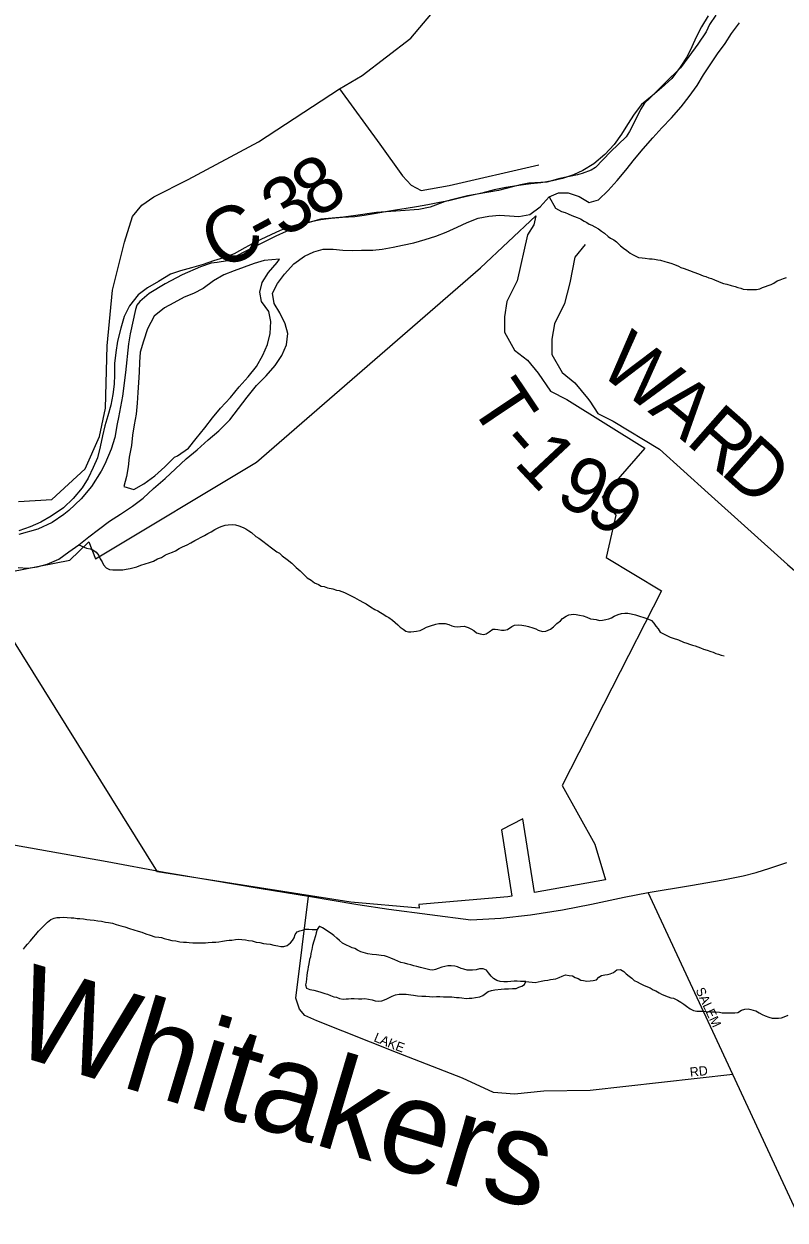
# Model space of a CAD drawing. Extents: x 0 to 1064, y 0 to 440.
# Drawn here: x 322.39 to 334.77, y 145.11 to 164.57 of the extents above; entities that cross this region are included whole.
import ezdxf

# ---------------------------------------------------------------- set-up
doc = ezdxf.new("R2010")
doc.units = 0
for name, color, linetype in [('GM_X_Corporation', 7, 'Continuous'), ('GM_X_County_Road', 7, 'Continuous'), ('GM_X_County_Road_Text', 7, 'Continuous'), ('GM_X_Major_River', 7, 'Continuous'), ('GM_X_Minor_Lake', 7, 'Continuous'), ('GM_X_Minor_River', 7, 'Continuous'), ('GM_X_Minor_River_Text', 7, 'Continuous'), ('GM_X_Section', 7, 'Continuous'), ('GM_X_Township_Road', 7, 'Continuous'), ('GM_X_Township_Road_Text', 7, 'Continuous'), ('GM_X_Township_Subdivision', 7, 'Continuous'), ('GM_X_Township_Subdivision_Text', 7, 'Continuous'), ('GM_X_US_Route', 7, 'Continuous')]:
    doc.layers.add(name, color=color, linetype=linetype)

msp = doc.modelspace()

# ---------------------------------------------------------------- linework, layer by layer
at = {"layer": 'GM_X_Corporation'}
msp.add_lwpolyline([(321.667, 155.562), (323.139, 155.848), (323.451, 156.149), (323.559, 155.869), (326.179, 157.444), (329.818, 160.607), (330.722, 161.45), (330.686, 161.304), (330.583, 161.143), (330.416, 160.393), (330.249, 160.06), (330.208, 159.809), (330.208, 159.559), (330.374, 159.268), (330.583, 159.101), (330.76, 158.891), (330.958, 158.601), (331.227, 158.466), (332.492, 157.672), (331.8, 156.876), (332.022, 156.581), (331.864, 155.893), (332.762, 155.353), (331.147, 152.183), (331.678, 151.227), (331.855, 150.647), (330.7, 150.443), (330.51, 151.641), (330.159, 151.462), (330.33, 150.384), (330.267, 150.373), (328.815, 150.246), (328.825, 150.186), (327.711, 150.284), (324.568, 150.782), (321.795, 155.22)], dxfattribs=at)
at = {"layer": 'GM_X_County_Road'}
msp.add_lwpolyline([(322.303, 156.803), (322.846, 156.838), (323.389, 157.338), (323.622, 157.859), (323.719, 158.325), (323.747, 159.339), (323.835, 160.244), (324.03, 161.024), (324.16, 161.44), (324.311, 161.625), (324.509, 161.763), (325.065, 162.043), (326.207, 162.655), (327.526, 163.517), (327.896, 163.733), (328.689, 164.344), (329.099, 164.829)], dxfattribs=at)
at = {"layer": 'GM_X_Major_River'}
for points in [[(333.522, 164.706), (333.415, 164.526), (333.326, 164.357), (333.256, 164.2), (333.179, 164.044), (333.066, 163.87), (332.934, 163.684), (332.766, 163.535), (332.611, 163.405), (332.437, 163.262), (332.318, 163.106), (332.21, 162.938), (332.116, 162.782), (331.996, 162.614), (331.84, 162.447), (331.666, 162.299), (331.487, 162.187), (331.333, 162.117), (331.155, 162.06), (330.989, 162.021), (330.799, 161.988), (330.64, 161.973), (330.481, 161.952), (330.23, 161.915), (330.04, 161.876), (329.844, 161.82), (329.691, 161.786), (329.501, 161.742), (329.304, 161.697), (329.151, 161.67), (328.961, 161.631), (328.778, 161.598), (328.612, 161.571), (328.435, 161.545), (328.276, 161.518), (328.092, 161.485), (327.927, 161.458), (327.774, 161.437), (327.578, 161.423), (327.389, 161.408), (327.223, 161.388), (327.064, 161.354), (326.911, 161.327), (326.739, 161.276), (326.561, 161.213), (326.407, 161.143), (326.166, 161.026), (325.988, 160.933), (325.815, 160.833), (325.642, 160.77), (325.477, 160.718), (325.311, 160.661), (325.12, 160.604), (324.942, 160.559), (324.777, 160.502)], [(326.645, 159.696), (326.557, 159.874), (326.463, 160.028), (326.436, 160.193), (326.518, 160.35), (326.632, 160.505), (326.781, 160.673), (326.955, 160.797), (327.109, 160.867), (327.262, 160.912), (327.421, 160.909), (327.579, 160.893), (327.732, 160.89), (327.884, 160.893), (328.067, 160.895), (328.22, 160.91), (328.398, 160.943), (328.551, 160.976), (328.735, 161.015), (328.919, 161.066), (329.091, 161.123), (329.263, 161.187), (329.442, 161.268), (329.602, 161.344), (329.781, 161.413), (329.958, 161.446), (330.129, 161.461), (330.294, 161.451), (330.446, 161.442), (330.624, 161.475), (330.791, 161.599), (330.935, 161.76), (331.089, 161.824), (331.247, 161.827), (331.423, 161.768), (331.586, 161.668), (331.739, 161.713), (331.895, 161.862), (332.045, 162.029), (332.183, 162.197), (332.327, 162.376), (332.464, 162.544), (332.621, 162.723), (332.771, 162.884), (332.926, 163.045), (333.083, 163.224), (333.214, 163.392), (333.346, 163.572), (333.448, 163.746), (333.567, 163.926), (333.674, 164.088), (333.8, 164.256), (333.901, 164.418), (334.033, 164.592)], [(326.551, 160.744), (326.301, 160.725), (326.141, 160.674), (325.975, 160.617), (325.815, 160.559), (325.643, 160.49), (325.476, 160.396), (325.309, 160.272), (325.154, 160.19), (325.001, 160.126), (324.834, 160.038), (324.68, 159.956), (324.512, 159.82), (324.404, 159.615), (324.339, 159.41), (324.286, 159.234), (324.271, 159.07), (324.267, 158.906), (324.258, 158.742), (324.248, 158.578), (324.238, 158.402), (324.217, 158.226), (324.188, 158.05), (324.161, 157.886), (324.145, 157.716), (324.104, 157.528), (324.089, 157.37), (324.061, 157.213), (324.021, 157.049), (324.179, 156.997), (324.345, 157.091), (324.525, 157.221), (324.687, 157.37), (324.843, 157.525), (324.892, 157.548)], [(324.892, 157.548), (325.071, 157.672), (325.197, 157.828), (325.335, 158.001), (325.46, 158.163), (325.591, 158.325), (325.754, 158.498), (325.892, 158.671), (326.041, 158.832), (326.179, 159), (326.281, 159.186), (326.357, 159.361), (326.398, 159.537), (326.408, 159.731), (326.375, 159.896), (326.256, 160.057), (326.229, 160.21), (326.269, 160.367), (326.37, 160.529), (326.513, 160.691), (326.551, 160.744)], [(324.777, 160.502), (324.585, 160.384), (324.406, 160.278), (324.251, 160.166), (324.113, 159.986), (324.024, 159.812), (323.971, 159.624), (323.918, 159.412), (323.89, 159.23), (323.868, 159.048), (323.864, 158.866), (323.861, 158.714), (323.839, 158.544), (323.805, 158.374), (323.758, 158.199), (323.712, 158.035), (323.672, 157.872), (323.632, 157.696), (323.592, 157.515), (323.521, 157.358), (323.438, 157.183), (323.343, 157.027), (323.193, 156.854), (323.038, 156.699), (322.839, 156.563), (322.667, 156.469), (322.494, 156.394), (322.31, 156.325)], [(322.297, 155.728), (322.456, 155.719), (322.609, 155.74), (322.774, 155.785), (322.959, 155.867), (323.126, 155.985), (323.287, 156.097), (323.449, 156.228), (323.604, 156.346), (323.784, 156.482), (323.963, 156.6), (324.161, 156.73), (324.334, 156.86), (324.502, 157.015), (324.689, 157.181), (324.857, 157.336), (325.031, 157.497), (325.211, 157.645), (325.391, 157.806), (325.565, 157.954), (325.74, 158.133), (325.884, 158.319), (326.022, 158.504), (326.179, 158.69), (326.335, 158.851), (326.478, 159.018), (326.586, 159.18), (326.662, 159.355), (326.685, 159.537), (326.645, 159.696)]]:
    msp.add_lwpolyline(points, dxfattribs=at)
at = {"layer": 'GM_X_Minor_Lake'}
for points in [[(327.197, 149.89), (327.162, 149.843), (327.148, 149.789), (327.135, 149.74), (327.108, 149.65), (327.088, 149.583), (327.075, 149.517), (327.061, 149.45), (327.053, 149.396), (327.04, 149.354), (327.026, 149.281), (327.019, 149.232), (327.012, 149.19), (326.998, 149.142), (326.997, 149.093), (326.99, 149.039), (326.982, 148.984), (326.975, 148.942), (326.992, 148.887), (327.046, 148.867), (327.107, 148.853), (327.167, 148.84), (327.221, 148.82), (327.288, 148.8), (327.33, 148.787), (327.378, 148.768), (327.433, 148.748), (327.475, 148.741), (327.529, 148.716), (327.584, 148.708), (327.633, 148.713), (327.675, 148.712), (327.718, 148.717), (327.767, 148.716), (327.834, 148.714), (327.888, 148.713), (327.937, 148.718), (327.998, 148.71), (328.058, 148.697), (328.107, 148.683), (328.161, 148.676), (328.216, 148.681), (328.284, 148.71), (328.327, 148.727), (328.383, 148.756), (328.438, 148.779), (328.499, 148.789), (328.554, 148.788), (328.609, 148.787)], [(330.556, 148.995), (330.513, 148.996), (330.471, 148.997), (330.416, 148.999), (330.367, 149), (330.312, 148.995), (330.257, 148.99), (330.197, 148.992), (330.142, 148.993), (330.087, 149.013), (330.033, 149.044), (329.992, 149.082), (329.951, 149.137), (329.915, 149.181), (329.861, 149.2), (329.806, 149.202), (329.751, 149.185), (329.69, 149.18), (329.647, 149.181), (329.605, 149.182), (329.55, 149.196), (329.508, 149.209), (329.448, 149.235), (329.405, 149.242), (329.345, 149.249), (329.29, 149.251), (329.241, 149.24), (329.192, 149.229), (329.13, 149.206), (329.087, 149.189), (329.045, 149.178), (328.996, 149.185), (328.954, 149.198), (328.911, 149.205), (328.845, 149.225), (328.784, 149.239), (328.736, 149.252), (328.688, 149.265), (328.639, 149.279), (328.585, 149.292), (328.524, 149.306), (328.476, 149.325), (328.428, 149.35), (328.362, 149.376), (328.307, 149.396), (328.259, 149.415), (328.204, 149.417), (328.126, 149.431), (328.059, 149.432), (327.986, 149.446), (327.913, 149.466), (327.871, 149.479), (327.817, 149.505), (327.775, 149.53), (327.733, 149.544), (327.691, 149.563), (327.643, 149.588), (327.576, 149.62), (327.529, 149.664), (327.481, 149.702), (327.433, 149.745), (327.392, 149.777), (327.35, 149.802), (327.308, 149.833), (327.248, 149.871), (327.206, 149.891), (327.197, 149.89)], [(328.609, 148.787), (328.688, 148.779), (328.73, 148.772), (328.797, 148.764), (328.864, 148.756), (328.93, 148.755), (328.991, 148.753), (329.046, 148.746), (329.107, 148.75), (329.156, 148.749), (329.216, 148.748), (329.259, 148.747), (329.356, 148.744), (329.429, 148.737), (329.472, 148.736), (329.514, 148.729), (329.587, 148.721), (329.636, 148.726), (329.678, 148.725), (329.74, 148.735), (329.807, 148.746), (329.856, 148.769), (329.899, 148.798), (329.943, 148.834), (329.998, 148.851), (330.053, 148.861), (330.157, 148.871), (330.212, 148.876), (330.273, 148.874), (330.34, 148.879), (330.401, 148.883), (330.444, 148.901), (330.493, 148.918), (330.536, 148.947), (330.556, 148.995)]]:
    msp.add_lwpolyline(points, dxfattribs=at)
at = {"layer": 'GM_X_Minor_River'}
for points in [[(330.935, 161.76), (331.041, 161.574), (331.089, 161.549), (331.137, 161.524), (331.198, 161.504), (331.246, 161.484), (331.306, 161.459), (331.348, 161.439), (331.391, 161.426), (331.445, 161.401), (331.505, 161.363), (331.547, 161.343), (331.589, 161.318), (331.631, 161.299), (331.679, 161.273), (331.739, 161.242), (331.787, 161.204), (331.835, 161.172), (331.894, 161.116), (331.936, 161.091), (331.99, 161.059), (332.032, 161.028), (332.098, 160.965), (332.145, 160.928), (332.199, 160.89), (332.253, 160.846), (332.295, 160.821), (332.349, 160.795), (332.391, 160.776), (332.452, 160.768), (332.5, 160.761), (332.567, 160.753), (332.61, 160.752), (332.652, 160.745), (332.707, 160.738), (332.749, 160.731), (332.816, 160.711), (332.858, 160.698), (332.918, 160.684), (332.973, 160.659), (333.039, 160.633), (333.081, 160.613), (333.135, 160.594), (333.178, 160.581), (333.22, 160.561), (333.292, 160.535), (333.364, 160.509), (333.443, 160.477), (333.485, 160.464), (333.533, 160.444), (333.576, 160.431), (333.624, 160.412), (333.69, 160.386), (333.732, 160.367), (333.774, 160.353), (333.829, 160.34), (333.895, 160.32), (333.962, 160.3), (334.004, 160.287), (334.053, 160.274), (334.095, 160.261), (334.156, 160.253), (334.198, 160.252), (334.259, 160.251), (334.308, 160.255), (334.363, 160.266), (334.406, 160.284), (334.455, 160.301), (334.498, 160.318), (334.547, 160.335), (334.59, 160.358), (334.646, 160.393), (334.695, 160.41), (334.751, 160.433), (334.8, 160.45)], [(323.287, 156.097), (323.409, 156.044), (323.47, 156.036), (323.512, 156.017), (323.566, 155.979), (323.613, 155.923), (323.636, 155.874), (323.665, 155.825), (323.688, 155.775), (323.73, 155.726), (323.784, 155.7), (323.839, 155.693), (323.893, 155.691), (323.948, 155.69), (324.003, 155.695), (324.058, 155.706), (324.119, 155.716), (324.187, 155.733), (324.229, 155.744), (324.297, 155.767), (324.365, 155.79), (324.438, 155.812), (324.5, 155.835), (324.567, 155.87), (324.629, 155.893), (324.697, 155.934), (324.752, 155.956), (324.808, 155.979), (324.857, 156.003), (324.919, 156.038), (324.974, 156.067), (325.048, 156.101), (325.11, 156.13), (325.172, 156.171), (325.215, 156.189), (325.276, 156.224), (325.332, 156.253), (325.387, 156.282), (325.437, 156.311), (325.499, 156.346), (325.573, 156.387), (325.616, 156.404), (325.665, 156.421), (325.714, 156.426), (325.781, 156.43), (325.835, 156.423), (325.89, 156.409), (325.962, 156.383), (326.004, 156.358), (326.052, 156.326), (326.094, 156.301), (326.165, 156.233), (326.213, 156.207), (326.279, 156.157), (326.351, 156.106), (326.423, 156.05), (326.506, 155.987), (326.548, 155.962), (326.596, 155.918), (326.673, 155.862), (326.751, 155.799), (326.822, 155.73), (326.888, 155.674), (326.953, 155.612), (327.001, 155.562), (327.067, 155.524), (327.12, 155.48), (327.187, 155.454), (327.229, 155.429), (327.277, 155.421), (327.332, 155.402), (327.416, 155.382), (327.477, 155.362), (327.519, 155.355), (327.567, 155.341), (327.61, 155.322), (327.718, 155.271), (327.772, 155.245), (327.844, 155.201), (327.916, 155.163), (327.958, 155.138), (328.03, 155.093), (328.102, 155.049), (328.15, 155.023), (328.192, 154.998), (328.246, 154.966), (328.288, 154.941), (328.33, 154.916), (328.39, 154.872), (328.431, 154.834), (328.473, 154.797), (328.515, 154.759), (328.563, 154.728), (328.604, 154.696), (328.647, 154.683), (328.689, 154.682), (328.738, 154.687), (328.781, 154.692), (328.836, 154.703), (328.891, 154.732), (328.941, 154.761)], [(328.941, 154.761), (329.008, 154.784), (329.094, 154.806), (329.143, 154.817), (329.204, 154.822), (329.247, 154.821), (329.307, 154.801), (329.355, 154.782), (329.398, 154.768), (329.44, 154.767), (329.495, 154.772), (329.556, 154.777), (329.617, 154.757), (329.665, 154.732), (329.713, 154.706), (329.754, 154.669), (329.815, 154.649), (329.869, 154.642), (329.912, 154.653), (329.962, 154.682), (330.018, 154.729), (330.06, 154.728), (330.103, 154.721), (330.163, 154.713), (330.206, 154.712), (330.261, 154.723), (330.329, 154.77), (330.372, 154.794), (330.433, 154.798), (330.494, 154.791), (330.555, 154.783), (330.603, 154.77), (330.669, 154.75), (330.718, 154.731), (330.76, 154.711), (330.826, 154.691), (330.881, 154.696), (330.961, 154.725), (331.005, 154.766), (331.061, 154.82), (331.123, 154.861), (331.154, 154.902), (331.216, 154.937), (331.259, 154.961), (331.332, 154.971), (331.375, 154.964), (331.43, 154.957), (331.49, 154.943), (331.55, 154.923), (331.611, 154.897), (331.659, 154.89), (331.702, 154.883), (331.756, 154.87), (331.805, 154.875), (331.86, 154.885), (331.909, 154.896), (331.952, 154.914), (331.995, 154.937), (332.057, 154.966), (332.112, 154.983), (332.167, 154.987), (332.216, 154.986), (332.27, 154.979), (332.343, 154.959), (332.391, 154.946), (332.494, 154.913), (332.542, 154.893), (332.602, 154.867), (332.638, 154.824), (332.673, 154.775), (332.708, 154.731), (332.743, 154.676), (332.786, 154.656), (332.84, 154.631), (332.906, 154.599), (332.954, 154.579), (333.039, 154.553), (333.123, 154.514), (333.177, 154.501), (333.22, 154.482), (333.268, 154.468), (333.31, 154.455), (333.401, 154.423), (333.449, 154.403), (333.509, 154.384), (333.564, 154.364), (333.606, 154.351), (333.648, 154.332), (333.69, 154.318), (333.733, 154.305), (333.781, 154.292)], [(322.387, 149.52), (322.419, 149.562), (322.45, 149.604), (322.5, 149.658), (322.55, 149.717), (322.588, 149.759), (322.632, 149.812), (322.676, 149.86), (322.72, 149.908), (322.776, 149.961), (322.832, 150.002), (322.887, 150.025), (322.93, 150.036), (322.978, 150.035), (323.033, 150.04), (323.094, 150.038), (323.161, 150.031), (323.204, 150.03), (323.258, 150.022), (323.301, 150.021), (323.361, 150.014), (323.416, 150.006), (323.471, 149.999), (323.537, 149.991), (323.598, 149.984), (323.653, 149.976), (323.719, 149.963), (323.768, 149.955), (323.834, 149.942), (323.895, 149.922), (323.967, 149.902), (324.034, 149.882), (324.112, 149.856), (324.179, 149.836), (324.251, 149.816), (324.312, 149.796), (324.378, 149.77), (324.445, 149.751), (324.523, 149.724), (324.59, 149.717), (324.632, 149.71), (324.675, 149.696), (324.741, 149.676), (324.801, 149.663), (324.862, 149.655), (324.929, 149.642), (324.989, 149.634), (325.038, 149.633), (325.081, 149.632), (325.141, 149.624), (325.196, 149.623), (325.257, 149.622), (325.306, 149.626), (325.348, 149.625), (325.391, 149.63), (325.458, 149.635), (325.513, 149.634), (325.562, 149.638), (325.623, 149.649), (325.69, 149.66), (325.733, 149.665), (325.776, 149.67), (325.837, 149.68), (325.88, 149.686), (325.94, 149.678), (325.995, 149.671), (326.049, 149.663), (326.104, 149.656), (326.171, 149.636), (326.231, 149.628), (326.292, 149.615), (326.34, 149.608), (326.401, 149.6), (326.461, 149.586), (326.522, 149.573), (326.571, 149.566), (326.619, 149.564), (326.674, 149.581), (326.73, 149.622), (326.762, 149.664), (326.787, 149.706), (326.807, 149.76), (326.838, 149.802), (326.881, 149.819), (326.924, 149.831), (326.973, 149.848), (327.028, 149.846), (327.083, 149.839)], [(327.083, 149.839), (327.162, 149.843)], [(330.556, 148.995), (330.708, 148.979), (330.757, 148.99), (330.805, 149.001), (330.861, 149.012), (330.915, 149.017), (330.958, 149.028), (331.001, 149.033), (331.044, 149.038), (331.099, 149.061), (331.148, 149.084), (331.204, 149.101), (331.264, 149.094), (331.319, 149.086), (331.361, 149.061), (331.409, 149.042), (331.451, 149.016), (331.494, 149.009), (331.548, 149.002), (331.603, 149.006), (331.652, 149.011), (331.707, 149.022), (331.745, 149.064), (331.788, 149.093), (331.843, 149.104), (331.886, 149.109), (331.929, 149.12), (331.984, 149.143), (332.04, 149.184), (332.095, 149.189), (332.149, 149.157), (332.19, 149.12), (332.238, 149.082), (332.28, 149.051), (332.322, 149.013), (332.37, 148.988), (332.418, 148.962), (332.472, 148.937), (332.538, 148.911), (332.58, 148.892), (332.628, 148.86), (332.67, 148.841), (332.724, 148.809), (332.766, 148.79), (332.827, 148.764), (332.875, 148.745), (332.917, 148.732), (332.96, 148.724), (333.026, 148.692), (333.08, 148.661), (333.128, 148.629), (333.169, 148.592), (333.229, 148.548), (333.283, 148.522), (333.338, 148.515), (333.393, 148.513), (333.435, 148.512), (333.49, 148.505), (333.551, 148.504), (333.605, 148.502), (333.648, 148.501), (333.709, 148.494), (333.751, 148.487), (333.806, 148.485), (333.855, 148.484), (333.909, 148.483), (333.958, 148.488), (334.007, 148.493), (334.063, 148.528), (334.118, 148.545), (334.173, 148.549), (334.215, 148.542), (334.257, 148.529), (334.3, 148.516), (334.354, 148.484), (334.402, 148.459), (334.45, 148.439), (334.51, 148.414), (334.565, 148.4), (334.607, 148.399), (334.668, 148.398), (334.717, 148.402), (334.76, 148.42), (334.822, 148.449)]]:
    msp.add_lwpolyline(points, dxfattribs=at)
at = {"layer": 'GM_X_Section'}
msp.add_lwpolyline([(333.647, 164.716), (333.547, 164.566), (333.491, 164.446), (333.354, 164.243), (333.211, 164.045), (333.075, 163.86), (332.816, 163.61), (332.575, 163.365), (332.489, 163.282), (332.421, 163.18), (332.377, 163.09), (332.245, 162.826), (332.189, 162.736), (331.936, 162.492), (331.689, 162.236), (331.622, 162.194), (331.476, 162.142), (331.396, 162.12), (331.111, 162.058), (330.898, 162.001), (330.606, 161.982), (330.473, 161.954), (330.363, 161.931), (330.113, 161.863), (329.609, 161.775), (329.372, 161.718), (329.244, 161.684), (329, 161.592), (328.818, 161.552), (328.52, 161.533), (328.126, 161.504), (327.792, 161.455), (327.591, 161.428), (327.221, 161.398), (326.935, 161.318), (326.661, 161.196), (326.489, 161.12), (325.97, 160.863), (325.707, 160.722), (325.537, 160.694), (325.44, 160.684), (325.263, 160.62), (324.97, 160.492), (324.689, 160.346), (324.431, 160.187), (324.278, 160.056), (324.228, 159.996), (324.209, 159.93), (324.123, 159.531), (324.096, 159.368), (324.046, 158.903), (323.996, 158.516), (323.93, 158.172), (323.91, 158.069), (323.87, 157.845), (323.812, 157.653), (323.711, 157.412), (323.648, 157.298), (323.492, 157.046), (323.325, 156.849), (323.122, 156.659), (323.042, 156.593), (322.852, 156.463), (322.62, 156.352), (322.309, 156.267)], dxfattribs=at)
at = {"layer": 'GM_X_Township_Road'}
for points in [[(327.526, 163.517), (328.185, 162.616), (328.551, 162.104), (328.694, 161.953), (328.854, 161.862), (329.313, 161.945), (330.771, 162.279)], [(331.521, 160.987), (331.355, 160.778), (331.271, 160.362), (331.188, 160.028), (331.021, 159.695), (330.979, 159.445), (330.979, 159.195), (331.146, 158.903), (331.355, 158.737), (331.563, 158.486), (331.597, 158.436)], [(331.597, 158.436), (331.729, 158.236), (331.979, 158.112), (332.73, 157.653), (333.524, 156.938), (334.813, 155.778), (335.396, 155.278), (335.771, 154.694), (337.156, 151.988)]]:
    msp.add_lwpolyline(points, dxfattribs=at)
at = {"layer": 'GM_X_Township_Subdivision'}
for points in [[(335.561, 143.959), (333.922, 147.481), (332.545, 150.442)], [(333.922, 147.481), (331.603, 147.222), (330.848, 147.213), (330.373, 147.164), (330.03, 147.187), (329.525, 147.421), (328.456, 147.839), (327.16, 148.353), (326.961, 148.442), (326.876, 148.544), (326.814, 148.726), (327.024, 150.385)]]:
    msp.add_lwpolyline(points, dxfattribs=at)
at = {"layer": 'GM_X_US_Route'}
msp.add_lwpolyline([(321.704, 151.311), (323.75, 150.949), (324.676, 150.776), (325.418, 150.649), (326.253, 150.506), (327.024, 150.385), (327.824, 150.247), (328.33, 150.172), (329.661, 149.998), (330.15, 150.027), (330.634, 150.081), (331.155, 150.163), (331.628, 150.253), (332.156, 150.366), (332.545, 150.442), (333.235, 150.555), (333.769, 150.649), (334.094, 150.713), (334.303, 150.768), (334.525, 150.841), (334.802, 150.93)], dxfattribs=at)

# ---------------------------------------------------------------- texts
at = {"layer": 'GM_X_County_Road_Text'}
for s, rotation, p in [('8', 32.9218, (327.137, 161.39)), ('3', 29.7407, (326.604, 161.083)), ('C', 27.951, (325.589, 160.541)), ('-', 28.4166, (326.255, 160.894))]:
    msp.add_text(s, height=0.909, rotation=rotation, dxfattribs=at).set_placement(p)
at = {"layer": 'GM_X_Minor_River_Text'}
msp.add_text('Whitakers', height=1.5151, rotation=343.3767, dxfattribs=at).set_placement((322.112, 147.839))
at = {"layer": 'GM_X_Township_Road_Text'}
for s, rotation, p in [('W', 321.4283, (331.712, 158.923)), ('T', 303.7638, (329.622, 158.393)), ('A', 320.2206, (332.531, 158.27)), ('R', 318.6287, (333.141, 157.762)), ('-', 311.1249, (330.077, 157.726)), ('1', 313.069, (330.345, 157.42)), ('D', 318.2551, (333.7, 157.27)), ('9', 333.5623, (331.01, 156.8)), ('9', 324.904, (331.48, 156.57))]:
    msp.add_text(s, height=0.909, rotation=rotation, dxfattribs=at).set_placement(p)
at = {"layer": 'GM_X_Township_Subdivision_Text'}
for s, height, rotation, p in [('SALEM', 0.1515, 294.9428, (333.315, 148.855)), ('L', 0.152, 337.6659, (328.073, 148.028)), ('A', 0.152, 337.6508, (328.172, 147.987)), ('K', 0.152, 337.6547, (328.295, 147.936)), ('E', 0.152, 339.6943, (328.424, 147.884)), ('RD', 0.1515, 6.3362, (333.233, 147.443))]:
    msp.add_text(s, height=height, rotation=rotation, dxfattribs=at).set_placement(p)

doc.saveas('drawing.dxf')
